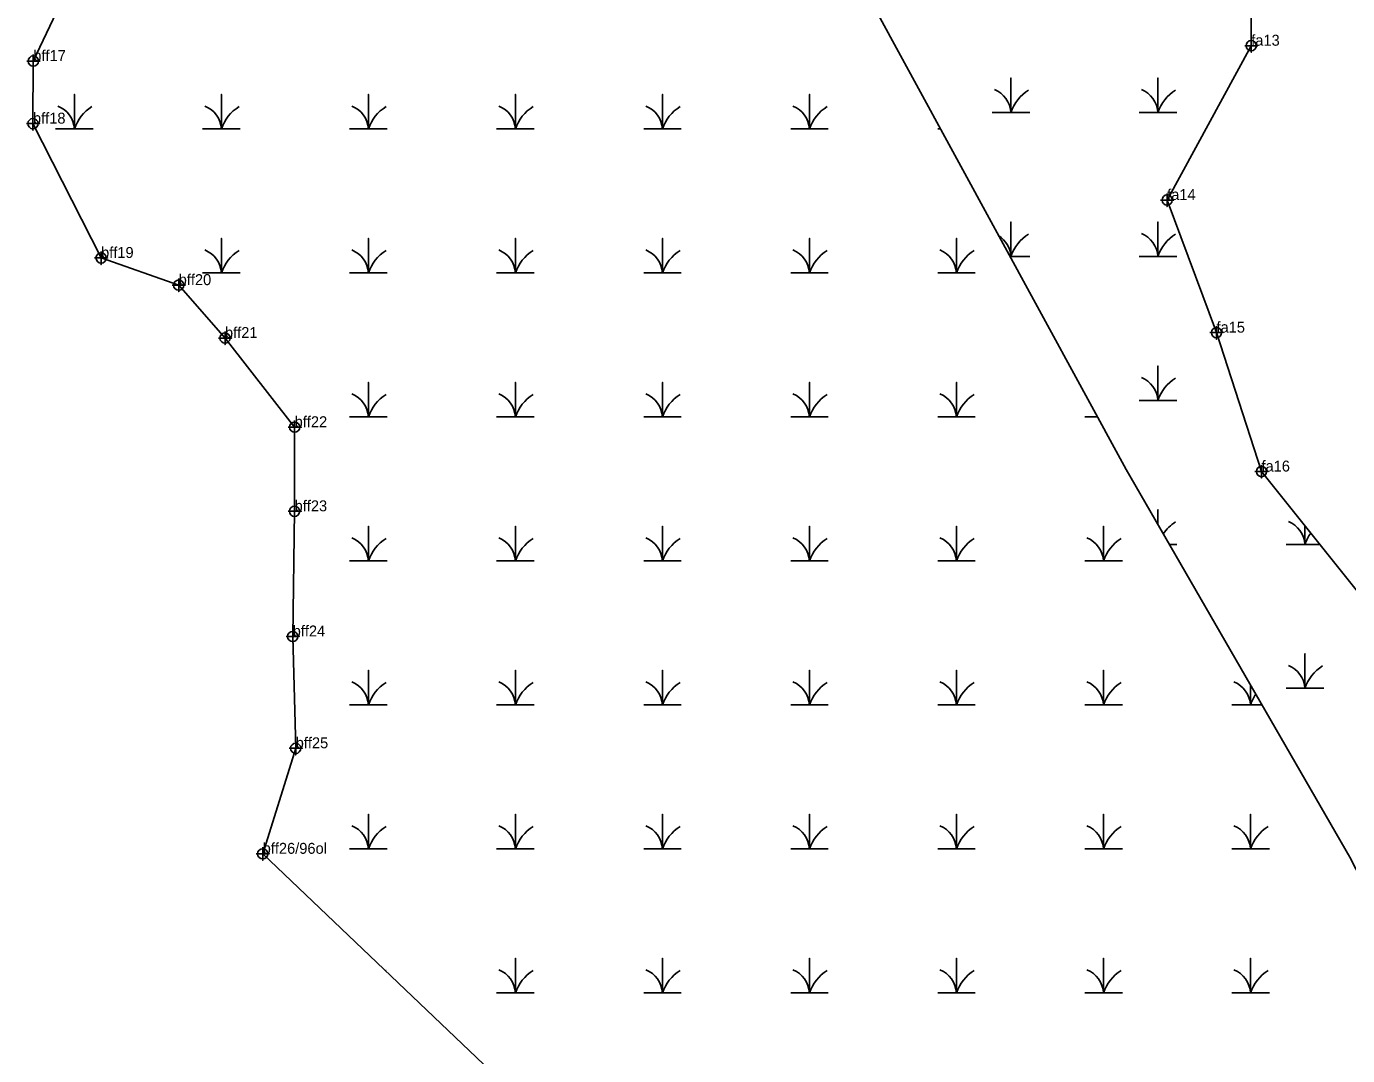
# Model space of a CAD drawing. Extents: x 2071991 to 2268989, y 436479 to 469629.
# Drawn here: x 2259914 to 2260518, y 440893 to 441363 of the extents above; entities that cross this region are included whole.
import ezdxf

# ---------------------------------------------------------------- set-up
doc = ezdxf.new("R2010")
doc.units = 0
for name, color, linetype in [('Exist Environmental Wetland Boundary', 7, 'Continuous'), ('Exist Environmental Wetland Boundary Cogo Comment', 7, 'Continuous'), ('Exist Environmental Wetland Boundary Cogo Point CELL', 7, 'Continuous'), ('Exist Hydro Jurisdictional Stream or Body of Water NEU Mitigable', 7, 'Continuous'), ('Exist Hydro Swamp or Marsh', 7, 'Continuous')]:
    doc.layers.add(name, color=color, linetype=linetype)

msp = doc.modelspace()

# ---------------------------------------------------------------- linework, layer by layer
at = {"layer": 'Exist Environmental Wetland Boundary'}
for points in [[(2260480.85, 442064.51), (2260471.33, 442023.13), (2260478.24, 441984.37), (2260453.18, 441919.62), (2260429.42, 441892.42), (2260405.4, 441828.34), (2260382.58, 441774.65), (2260378.54, 441677.46), (2260371.11, 441593.52), (2260413.53, 441501.55), (2260451.72, 441470.49), (2260474.35, 441433.89), (2260474.01, 441354.15), (2260435.58, 441283.64), (2260458.13, 441223.04), (2260478.69, 441159.57), (2260523.25, 441103.96), (2260546.39, 441048.63)], [(2259927.88, 441369.5), (2259917.27, 441347.14), (2259917.12, 441318.54), (2259948.25, 441257.17), (2259983.73, 441244.76), (2260004.9, 441220.59), (2260036.74, 441179.84), (2260036.72, 441141.41), (2260035.84, 441084.23), (2260037.21, 441033.13), (2260022.12, 440984.92), (2260136.15, 440876.39), (2260361.96, 440563.86), (2260493.56, 440418.63), (2260515.86, 440299.04)]]:
    msp.add_lwpolyline(points, dxfattribs=at)
at = {"layer": 'Exist Environmental Wetland Boundary Cogo Point CELL'}
for points in [[(2260474.01, 441357.15), (2260474.01, 441351.15), (2260474.01, 441354.15), (2260477.01, 441354.15), (2260471.01, 441354.15)], [(2259917.27, 441350.14), (2259917.27, 441344.14), (2259917.27, 441347.14), (2259920.27, 441347.14), (2259914.27, 441347.14)], [(2259917.12, 441321.54), (2259917.12, 441315.54), (2259917.12, 441318.54), (2259920.12, 441318.54), (2259914.12, 441318.54)], [(2260435.58, 441286.64), (2260435.58, 441280.64), (2260435.58, 441283.64), (2260438.58, 441283.64), (2260432.58, 441283.64)], [(2259948.25, 441260.17), (2259948.25, 441254.17), (2259948.25, 441257.17), (2259951.25, 441257.17), (2259945.25, 441257.17)], [(2259983.73, 441247.76), (2259983.73, 441241.76), (2259983.73, 441244.76), (2259986.73, 441244.76), (2259980.73, 441244.76)], [(2260458.13, 441226.04), (2260458.13, 441220.04), (2260458.13, 441223.04), (2260461.13, 441223.04), (2260455.13, 441223.04)], [(2260004.9, 441223.59), (2260004.9, 441217.59), (2260004.9, 441220.59), (2260007.9, 441220.59), (2260001.9, 441220.59)], [(2260036.74, 441182.84), (2260036.74, 441176.84), (2260036.74, 441179.84), (2260039.74, 441179.84), (2260033.74, 441179.84)], [(2260478.69, 441162.57), (2260478.69, 441156.57), (2260478.69, 441159.57), (2260481.69, 441159.57), (2260475.69, 441159.57)], [(2260036.72, 441144.41), (2260036.72, 441138.41), (2260036.72, 441141.41), (2260039.72, 441141.41), (2260033.72, 441141.41)], [(2260035.84, 441087.23), (2260035.84, 441081.23), (2260035.84, 441084.23), (2260038.84, 441084.23), (2260032.84, 441084.23)], [(2260037.21, 441036.13), (2260037.21, 441030.13), (2260037.21, 441033.13), (2260040.21, 441033.13), (2260034.21, 441033.13)], [(2260022.12, 440987.92), (2260022.12, 440981.92), (2260022.12, 440984.92), (2260025.12, 440984.92), (2260019.12, 440984.92)]]:
    msp.add_lwpolyline(points, dxfattribs=at)
for centre in [(2260474.01, 441354.15), (2259917.27, 441347.14), (2259917.12, 441318.54), (2260435.58, 441283.64), (2259948.25, 441257.17), (2259983.73, 441244.76), (2260458.13, 441223.04), (2260004.9, 441220.59), (2260036.74, 441179.84), (2260478.69, 441159.57), (2260036.72, 441141.41), (2260035.84, 441084.23), (2260037.21, 441033.13), (2260022.12, 440984.92)]:
    msp.add_circle(centre, 2.34, dxfattribs=at)
at = {"layer": 'Exist Hydro Jurisdictional Stream or Body of Water NEU Mitigable'}
msp.add_lwpolyline([(2260075.45, 441954.42), (2260114.02, 441801.94), (2260184.81, 441648.46), (2260298.86, 441376.92), (2260416.84, 441160.47), (2260519.09, 440983.38), (2260589.88, 440845.64), (2260656.73, 440711.84), (2260727.52, 440609.51), (2260817.97, 440519), (2260888.76, 440463.9), (2260939.89, 440416.68), (2260956.11, 440384.21)], dxfattribs=at)
at = {"layer": 'Exist Hydro Swamp or Marsh'}
for p, q in [((2260330.69, 441316.11), (2260332.01, 441316.11)), ((2260397.89, 441184.55), (2260403.72, 441184.55)), ((2260436.56, 441126.32), (2260439.98, 441126.32))]:
    msp.add_line(p, q, dxfattribs=at)
for points in [[(2260355.57, 441323.66), (2260364.18, 441323.66), (2260364.18, 441339.45), (2260364.18, 441323.66), (2260372.78, 441323.66)], [(2260422.78, 441323.66), (2260431.38, 441323.66), (2260431.38, 441339.45), (2260431.38, 441323.66), (2260439.98, 441323.66)], [(2259927.47, 441316.11), (2259936.07, 441316.11), (2259936.07, 441331.89), (2259936.07, 441316.11), (2259944.68, 441316.11)], [(2259994.68, 441316.11), (2260003.28, 441316.11), (2260003.28, 441331.89), (2260003.28, 441316.11), (2260011.88, 441316.11)], [(2260061.88, 441316.11), (2260070.48, 441316.11), (2260070.48, 441331.89), (2260070.48, 441316.11), (2260079.08, 441316.11)], [(2260129.08, 441316.11), (2260137.68, 441316.11), (2260137.68, 441331.89), (2260137.68, 441316.11), (2260146.29, 441316.11)], [(2260196.29, 441316.11), (2260204.89, 441316.11), (2260204.89, 441331.89), (2260204.89, 441316.11), (2260213.49, 441316.11)], [(2260263.49, 441316.11), (2260272.09, 441316.11), (2260272.09, 441331.89), (2260272.09, 441316.11), (2260280.69, 441316.11)], [(2260363.74, 441257.88), (2260364.18, 441257.88), (2260364.18, 441273.66), (2260364.18, 441257.88), (2260372.78, 441257.88)], [(2260422.78, 441257.88), (2260431.38, 441257.88), (2260431.38, 441273.66), (2260431.38, 441257.88), (2260439.98, 441257.88)], [(2259994.68, 441250.33), (2260003.28, 441250.33), (2260003.28, 441266.11), (2260003.28, 441250.33), (2260011.88, 441250.33)], [(2260061.88, 441250.33), (2260070.48, 441250.33), (2260070.48, 441266.11), (2260070.48, 441250.33), (2260079.08, 441250.33)], [(2260129.08, 441250.33), (2260137.68, 441250.33), (2260137.68, 441266.11), (2260137.68, 441250.33), (2260146.29, 441250.33)], [(2260196.29, 441250.33), (2260204.89, 441250.33), (2260204.89, 441266.11), (2260204.89, 441250.33), (2260213.49, 441250.33)], [(2260263.49, 441250.33), (2260272.09, 441250.33), (2260272.09, 441266.11), (2260272.09, 441250.33), (2260280.69, 441250.33)], [(2260330.69, 441250.33), (2260339.29, 441250.33), (2260339.29, 441266.11), (2260339.29, 441250.33), (2260347.89, 441250.33)], [(2260422.78, 441192.1), (2260431.38, 441192.1), (2260431.38, 441207.88), (2260431.38, 441192.1), (2260439.98, 441192.1)], [(2260061.88, 441184.55), (2260070.48, 441184.55), (2260070.48, 441200.33), (2260070.48, 441184.55), (2260079.08, 441184.55)], [(2260129.08, 441184.55), (2260137.68, 441184.55), (2260137.68, 441200.33), (2260137.68, 441184.55), (2260146.29, 441184.55)], [(2260196.29, 441184.55), (2260204.89, 441184.55), (2260204.89, 441200.33), (2260204.89, 441184.55), (2260213.49, 441184.55)], [(2260263.49, 441184.55), (2260272.09, 441184.55), (2260272.09, 441200.33), (2260272.09, 441184.55), (2260280.69, 441184.55)], [(2260330.69, 441184.55), (2260339.29, 441184.55), (2260339.29, 441200.33), (2260339.29, 441184.55), (2260347.89, 441184.55)], [(2260431.38, 441135.29), (2260431.38, 441142.1), (2260431.38, 441135.29)], [(2260061.88, 441118.77), (2260070.48, 441118.77), (2260070.48, 441134.55), (2260070.48, 441118.77), (2260079.08, 441118.77)], [(2260129.08, 441118.77), (2260137.68, 441118.77), (2260137.68, 441134.55), (2260137.68, 441118.77), (2260146.29, 441118.77)], [(2260196.29, 441118.77), (2260204.89, 441118.77), (2260204.89, 441134.55), (2260204.89, 441118.77), (2260213.49, 441118.77)], [(2260263.49, 441118.77), (2260272.09, 441118.77), (2260272.09, 441134.55), (2260272.09, 441118.77), (2260280.69, 441118.77)], [(2260330.69, 441118.77), (2260339.29, 441118.77), (2260339.29, 441134.55), (2260339.29, 441118.77), (2260347.89, 441118.77)], [(2260397.89, 441118.77), (2260406.5, 441118.77), (2260406.5, 441134.55), (2260406.5, 441118.77), (2260415.1, 441118.77)], [(2260489.98, 441126.32), (2260498.58, 441126.32), (2260498.58, 441134.74)], [(2260498.58, 441134.74), (2260498.58, 441126.32), (2260505.32, 441126.32)], [(2260489.98, 441060.54), (2260498.58, 441060.54), (2260498.58, 441076.32), (2260498.58, 441060.54), (2260507.18, 441060.54)], [(2260061.88, 441052.99), (2260070.48, 441052.99), (2260070.48, 441068.77), (2260070.48, 441052.99), (2260079.08, 441052.99)], [(2260129.08, 441052.99), (2260137.68, 441052.99), (2260137.68, 441068.77), (2260137.68, 441052.99), (2260146.29, 441052.99)], [(2260196.29, 441052.99), (2260204.89, 441052.99), (2260204.89, 441068.77), (2260204.89, 441052.99), (2260213.49, 441052.99)], [(2260263.49, 441052.99), (2260272.09, 441052.99), (2260272.09, 441068.77), (2260272.09, 441052.99), (2260280.69, 441052.99)], [(2260330.69, 441052.99), (2260339.29, 441052.99), (2260339.29, 441068.77), (2260339.29, 441052.99), (2260347.89, 441052.99)], [(2260397.89, 441052.99), (2260406.5, 441052.99), (2260406.5, 441068.77), (2260406.5, 441052.99), (2260415.1, 441052.99)], [(2260465.1, 441052.99), (2260473.7, 441052.99), (2260473.7, 441061.99)], [(2260473.7, 441061.99), (2260473.7, 441052.99), (2260478.9, 441052.99)], [(2260061.88, 440987.21), (2260070.48, 440987.21), (2260070.48, 441002.99), (2260070.48, 440987.21), (2260079.08, 440987.21)], [(2260129.08, 440987.21), (2260137.68, 440987.21), (2260137.68, 441002.99), (2260137.68, 440987.21), (2260146.29, 440987.21)], [(2260196.29, 440987.21), (2260204.89, 440987.21), (2260204.89, 441002.99), (2260204.89, 440987.21), (2260213.49, 440987.21)], [(2260263.49, 440987.21), (2260272.09, 440987.21), (2260272.09, 441002.99), (2260272.09, 440987.21), (2260280.69, 440987.21)], [(2260330.69, 440987.21), (2260339.29, 440987.21), (2260339.29, 441002.99), (2260339.29, 440987.21), (2260347.89, 440987.21)], [(2260397.89, 440987.21), (2260406.5, 440987.21), (2260406.5, 441002.99), (2260406.5, 440987.21), (2260415.1, 440987.21)], [(2260465.1, 440987.21), (2260473.7, 440987.21), (2260473.7, 441002.99), (2260473.7, 440987.21), (2260482.3, 440987.21)], [(2260129.08, 440921.43), (2260137.68, 440921.43), (2260137.68, 440937.21), (2260137.68, 440921.43), (2260146.29, 440921.43)], [(2260196.29, 440921.43), (2260204.89, 440921.43), (2260204.89, 440937.21), (2260204.89, 440921.43), (2260213.49, 440921.43)], [(2260263.49, 440921.43), (2260272.09, 440921.43), (2260272.09, 440937.21), (2260272.09, 440921.43), (2260280.69, 440921.43)], [(2260330.69, 440921.43), (2260339.29, 440921.43), (2260339.29, 440937.21), (2260339.29, 440921.43), (2260347.89, 440921.43)], [(2260397.89, 440921.43), (2260406.5, 440921.43), (2260406.5, 440937.21), (2260406.5, 440921.43), (2260415.1, 440921.43)], [(2260465.1, 440921.43), (2260473.7, 440921.43), (2260473.7, 440937.21), (2260473.7, 440921.43), (2260482.3, 440921.43)]]:
    msp.add_lwpolyline(points, dxfattribs=at)
for centre, radius, start, end in [((2260351.91, 441322.78), 12.3, 4.14034, 67.53497), ((2260382.42, 441317.6), 19.22, 122.12745, 161.62219), ((2260419.11, 441322.78), 12.3, 4.14034, 67.53497), ((2260449.62, 441317.6), 19.22, 122.12745, 161.62219), ((2259923.81, 441315.22), 12.3, 4.14034, 67.53497), ((2259954.32, 441310.05), 19.22, 122.12745, 161.62219), ((2259991.01, 441315.22), 12.3, 4.14034, 67.53497), ((2260021.52, 441310.05), 19.22, 122.12745, 161.62219), ((2260058.21, 441315.22), 12.3, 4.14034, 67.53497), ((2260088.72, 441310.05), 19.22, 122.12745, 161.62219), ((2260125.42, 441315.22), 12.3, 4.14034, 67.53497), ((2260155.93, 441310.05), 19.22, 122.12745, 161.62219), ((2260192.62, 441315.22), 12.3, 4.14034, 67.53497), ((2260223.13, 441310.05), 19.22, 122.12745, 161.62219), ((2260259.82, 441315.22), 12.3, 4.14034, 67.53497), ((2260290.33, 441310.05), 19.22, 122.12745, 161.62219), ((2260351.91, 441257), 12.3, 4.14034, 57.03193), ((2260382.42, 441251.82), 19.22, 122.12745, 161.62219), ((2260419.11, 441257), 12.3, 4.14034, 67.53497), ((2260449.62, 441251.82), 19.22, 122.12745, 161.62219), ((2259991.01, 441249.44), 12.3, 4.14034, 67.53497), ((2260021.52, 441244.27), 19.22, 122.12745, 161.62219), ((2260058.21, 441249.44), 12.3, 4.14034, 67.53497), ((2260088.72, 441244.27), 19.22, 122.12745, 161.62219), ((2260125.42, 441249.44), 12.3, 4.14034, 67.53497), ((2260155.93, 441244.27), 19.22, 122.12745, 161.62219), ((2260192.62, 441249.44), 12.3, 4.14034, 67.53497), ((2260223.13, 441244.27), 19.22, 122.12745, 161.62219), ((2260259.82, 441249.44), 12.3, 4.14034, 67.53497), ((2260290.33, 441244.27), 19.22, 122.12745, 161.62219), ((2260327.03, 441249.44), 12.3, 4.14034, 67.53497), ((2260357.54, 441244.27), 19.22, 122.12745, 161.62219), ((2260419.11, 441191.22), 12.3, 4.14034, 67.53497), ((2260449.62, 441186.04), 19.22, 122.12745, 161.62219), ((2260058.21, 441183.66), 12.3, 4.14034, 67.53497), ((2260088.72, 441178.49), 19.22, 122.12745, 161.62219), ((2260125.42, 441183.66), 12.3, 4.14034, 67.53497), ((2260155.93, 441178.49), 19.22, 122.12745, 161.62219), ((2260192.62, 441183.66), 12.3, 4.14034, 67.53497), ((2260223.13, 441178.49), 19.22, 122.12745, 161.62219), ((2260259.82, 441183.66), 12.3, 4.14034, 67.53497), ((2260290.33, 441178.49), 19.22, 122.12745, 161.62219), ((2260327.03, 441183.66), 12.3, 4.14034, 67.53497), ((2260357.54, 441178.49), 19.22, 122.12745, 161.62219), ((2260449.62, 441120.26), 19.22, 122.12745, 145.5298), ((2260486.32, 441125.43), 12.3, 4.14034, 67.53497), ((2260058.21, 441117.88), 12.3, 4.14034, 67.53497), ((2260088.72, 441112.71), 19.22, 122.12745, 161.62219), ((2260125.42, 441117.88), 12.3, 4.14034, 67.53497), ((2260155.93, 441112.71), 19.22, 122.12745, 161.62219), ((2260192.62, 441117.88), 12.3, 4.14034, 67.53497), ((2260223.13, 441112.71), 19.22, 122.12745, 161.62219), ((2260259.82, 441117.88), 12.3, 4.14034, 67.53497), ((2260290.33, 441112.71), 19.22, 122.12745, 161.62219), ((2260327.03, 441117.88), 12.3, 4.14034, 67.53497), ((2260357.54, 441112.71), 19.22, 122.12745, 161.62219), ((2260394.23, 441117.88), 12.3, 4.14034, 67.53497), ((2260424.74, 441112.71), 19.22, 122.12745, 161.62219), ((2260516.82, 441120.26), 19.22, 144.35504, 161.62219), ((2260486.32, 441059.65), 12.3, 4.14034, 67.53497), ((2260516.82, 441054.48), 19.22, 122.12745, 161.62219), ((2260058.21, 441052.1), 12.3, 4.14034, 67.53497), ((2260088.72, 441046.93), 19.22, 122.12745, 161.62219), ((2260125.42, 441052.1), 12.3, 4.14034, 67.53497), ((2260155.93, 441046.93), 19.22, 122.12745, 161.62219), ((2260192.62, 441052.1), 12.3, 4.14034, 67.53497), ((2260223.13, 441046.93), 19.22, 122.12745, 161.62219), ((2260259.82, 441052.1), 12.3, 4.14034, 67.53497), ((2260290.33, 441046.93), 19.22, 122.12745, 161.62219), ((2260327.03, 441052.1), 12.3, 4.14034, 67.53497), ((2260357.54, 441046.93), 19.22, 122.12745, 161.62219), ((2260394.23, 441052.1), 12.3, 4.14034, 67.53497), ((2260424.74, 441046.93), 19.22, 122.12745, 161.62219), ((2260461.43, 441052.1), 12.3, 4.14034, 67.53497), ((2260491.94, 441046.93), 19.22, 145.46536, 161.62219), ((2260058.21, 440986.32), 12.3, 4.14034, 67.53497), ((2260088.72, 440981.15), 19.22, 122.12745, 161.62219), ((2260125.42, 440986.32), 12.3, 4.14034, 67.53497), ((2260155.93, 440981.15), 19.22, 122.12745, 161.62219), ((2260192.62, 440986.32), 12.3, 4.14034, 67.53497), ((2260223.13, 440981.15), 19.22, 122.12745, 161.62219), ((2260259.82, 440986.32), 12.3, 4.14034, 67.53497), ((2260290.33, 440981.15), 19.22, 122.12745, 161.62219), ((2260327.03, 440986.32), 12.3, 4.14034, 67.53497), ((2260357.54, 440981.15), 19.22, 122.12745, 161.62219), ((2260394.23, 440986.32), 12.3, 4.14034, 67.53497), ((2260424.74, 440981.15), 19.22, 122.12745, 161.62219), ((2260461.43, 440986.32), 12.3, 4.14034, 67.53497), ((2260491.94, 440981.15), 19.22, 122.12745, 161.62219), ((2260088.72, 440915.36), 19.22, 122.12745, 122.99047), ((2260125.42, 440920.54), 12.3, 4.14034, 67.53497), ((2260155.93, 440915.36), 19.22, 122.12745, 161.62219), ((2260192.62, 440920.54), 12.3, 4.14034, 67.53497), ((2260223.13, 440915.36), 19.22, 122.12745, 161.62219), ((2260259.82, 440920.54), 12.3, 4.14034, 67.53497), ((2260290.33, 440915.36), 19.22, 122.12745, 161.62219), ((2260327.03, 440920.54), 12.3, 4.14034, 67.53497), ((2260357.54, 440915.36), 19.22, 122.12745, 161.62219), ((2260394.23, 440920.54), 12.3, 4.14034, 67.53497), ((2260424.74, 440915.36), 19.22, 122.12745, 161.62219), ((2260461.43, 440920.54), 12.3, 4.14034, 67.53497), ((2260491.94, 440915.36), 19.22, 122.12745, 161.62219)]:
    msp.add_arc(centre, radius, start, end, dxfattribs=at)

# ---------------------------------------------------------------- texts
at = {"layer": 'Exist Environmental Wetland Boundary Cogo Comment'}
for s, p in [('fa13', (2260474.01, 441354.15)), ('bff17', (2259917.27, 441347.14)), ('bff18', (2259917.12, 441318.54)), ('fa14', (2260435.58, 441283.64)), ('bff19', (2259948.25, 441257.17)), ('bff20', (2259983.73, 441244.76)), ('bff21', (2260004.9, 441220.59)), ('fa15', (2260458.13, 441223.04)), ('bff22', (2260036.74, 441179.84)), ('fa16', (2260478.69, 441159.57)), ('bff23', (2260036.72, 441141.41)), ('bff24', (2260035.84, 441084.23)), ('bff25', (2260037.21, 441033.13)), ('bff26/96ol', (2260022.12, 440984.92))]:
    msp.add_text(s, height=5, dxfattribs=at).set_placement(p)

doc.saveas('drawing.dxf')
